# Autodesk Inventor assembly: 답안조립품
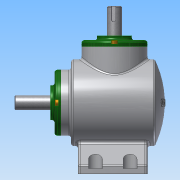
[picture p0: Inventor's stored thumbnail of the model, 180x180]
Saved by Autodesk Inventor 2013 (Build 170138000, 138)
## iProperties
Created: 2017-04
Part Number: 답안조립품
Document SubType Name: Assembly
Designer: Administrator
Author: Administrator
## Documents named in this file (14)
- C:\Users\Administrator\Desktop\470407V1006\답안조립품.iam
- C:\Users\Administrator\Desktop\470407V1006\본체.ipt
- C:\Users\Administrator\Desktop\470407V1006\메인 축.ipt
- 메인 축.ipt
- C:\Users\Administrator\Desktop\470407V1006\커버.ipt
- C:\Users\Administrator\Desktop\470407V1006\오일실 17 32 8.ipt
- C:\Users\Administrator\Desktop\470407V1006\베어링 6203.ipt
- C:\Users\Administrator\Desktop\470407V1006\키 5x5.ipt
- C:\Users\Administrator\Desktop\470407V1006\메인 베벨기어.ipt
- C:\Users\Administrator\Desktop\470407V1006\서브 축.ipt
- 서브 축.ipt
- C:\Users\Administrator\Desktop\470407V1006\키 4x4.ipt
- C:\Users\Administrator\Desktop\470407V1006\서브 베벨기어.ipt
- C:\Users\Administrator\Desktop\470407V1006\볼트 M4.ipt
